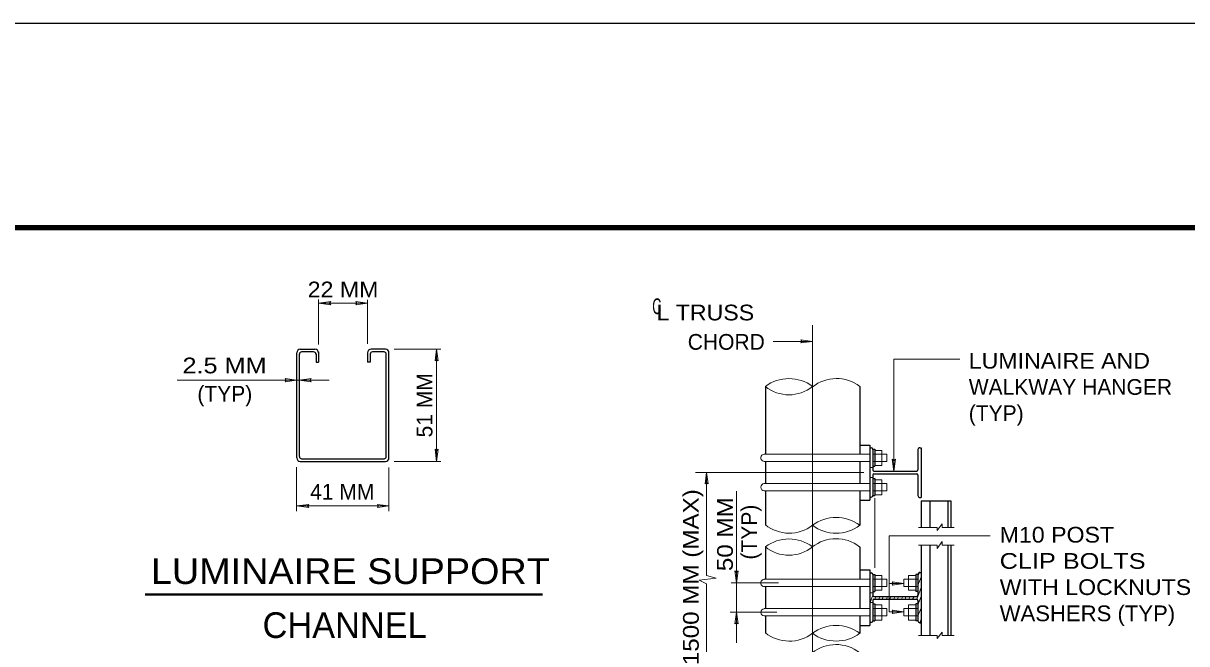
# Model space of a CAD drawing. Extents: x 312601.858 to 312602.699, y 144420.109 to 144420.704.
# Drawn here: x 312602.0414 to 312602.2633, y 144420.5851 to 144420.7035 of the extents above; entities that cross this region are included whole.
import ezdxf
from ezdxf.enums import TextEntityAlignment as Align

# ---------------------------------------------------------------- set-up
doc = ezdxf.new("R2010")
doc.units = 0
doc.header["$LTSCALE"] = 0.0012
doc.linetypes.add('DOT_DASHED', pattern=[7.7, 5, -1.2, 0.3, -1.2])
doc.linetypes.add('MEDIUM_DASHED', pattern=[4.5, 3, -1.5])
for name, color, linetype, lineweight in [('1', 7, 'Continuous', 13), ('2', 7, 'Continuous', 13), ('39', 7, 'Continuous', 13)]:
    doc.layers.add(name, color=color, linetype=linetype, lineweight=lineweight)

msp = doc.modelspace()

# ---------------------------------------------------------------- linework, layer by layer
at = {"layer": '1'}
for p, q in [((312602.0977, 144420.6508), (312602.0977, 144420.6422)), ((312602.0977, 144420.6504), (312602.0977, 144420.646)), ((312602.0977, 144420.6501), (312602.107, 144420.6501)), ((312602.107, 144420.6507), (312602.107, 144420.6423)), ((312602.121, 144420.6413), (312602.1121, 144420.6413)), ((312602.1202, 144420.6199), (312602.1202, 144420.6413)), ((312602.2074, 144420.6394), (312602.2074, 144420.618)), ((312602.22, 144420.6394), (312602.2074, 144420.6394)), ((312602.1827, 144420.6213), (312602.2009, 144420.6213)), ((312602.2051, 144420.6213), (312602.2061, 144420.6213)), ((312602.2061, 144420.6213), (312602.2061, 144420.6199)), ((312602.0935, 144420.6188), (312602.0935, 144420.6104)), ((312602.1111, 144420.6104), (312602.1111, 144420.6187)), ((312602.1121, 144420.6199), (312602.121, 144420.6199)), ((312602.2009, 144420.6199), (312602.1827, 144420.6199)), ((312602.2028, 144420.6187), (312602.2034, 144420.6187)), ((312602.2038, 144420.6191), (312602.2051, 144420.6191)), ((312602.2061, 144420.6199), (312602.2051, 144420.6199)), ((312602.2017, 144420.6178), (312602.1696, 144420.6178)), ((312602.1717, 144420.6178), (312602.1717, 144420.5981)), ((312602.2028, 144420.6168), (312602.2034, 144420.6168)), ((312602.2038, 144420.6164), (312602.2051, 144420.6164)), ((312602.2051, 144420.6135), (312602.2051, 144420.6164)), ((312602.2009, 144420.6157), (312602.1827, 144420.6157)), ((312602.1827, 144420.6143), (312602.2009, 144420.6143)), ((312602.2061, 144420.6157), (312602.2051, 144420.6157)), ((312602.2051, 144420.6143), (312602.2061, 144420.6143)), ((312602.2061, 144420.6143), (312602.2061, 144420.6157)), ((312602.2038, 144420.6135), (312602.2051, 144420.6135)), ((312602.2038, 144420.6129), (312602.2038, 144420.5996)), ((312602.0935, 144420.6114), (312602.1111, 144420.6114)), ((312602.2157, 144420.6067), (312602.2166, 144420.608)), ((312602.2166, 144420.6073), (312602.2166, 144420.608)), ((312602.2065, 144420.5912), (312602.2065, 144420.6057)), ((312602.2258, 144420.6057), (312602.2065, 144420.6057)), ((312602.2121, 144420.6073), (312602.2157, 144420.6073)), ((312602.2157, 144420.6067), (312602.2157, 144420.6073)), ((312602.2166, 144420.6073), (312602.2189, 144420.6073)), ((312602.2121, 144420.6039), (312602.2157, 144420.6039)), ((312602.2157, 144420.6033), (312602.2166, 144420.6046)), ((312602.2157, 144420.6033), (312602.2157, 144420.6039)), ((312602.2166, 144420.6039), (312602.2166, 144420.6046)), ((312602.2166, 144420.6039), (312602.2189, 144420.6039)), ((312602.2028, 144420.5992), (312602.2028, 144420.5902)), ((312602.212, 144420.598), (312602.2123, 144420.5987)), ((312602.1854, 144420.5967), (312602.1764, 144420.5967)), ((312602.1827, 144420.5974), (312602.2009, 144420.5974)), ((312602.2051, 144420.5974), (312602.2061, 144420.5974)), ((312602.2061, 144420.5974), (312602.2061, 144420.596)), ((312602.2093, 144420.5966), (312602.2065, 144420.5966)), ((312602.2093, 144420.5974), (312602.2093, 144420.596)), ((312602.2102, 144420.5974), (312602.2093, 144420.5974)), ((312602.2116, 144420.5981), (312602.2102, 144420.5981)), ((312602.2102, 144420.5981), (312602.2102, 144420.5953)), ((312602.212, 144420.5963), (312602.2126, 144420.5978)), ((312602.2009, 144420.596), (312602.1827, 144420.596)), ((312602.2028, 144420.5948), (312602.2034, 144420.5948)), ((312602.2029, 144420.593), (312602.2034, 144420.5944)), ((312602.2038, 144420.5953), (312602.2051, 144420.5953)), ((312602.2038, 144420.5936), (312602.204, 144420.5941)), ((312602.2046, 144420.5936), (312602.2047, 144420.5941)), ((312602.2061, 144420.596), (312602.2051, 144420.596)), ((312602.2052, 144420.5936), (312602.2054, 144420.5941)), ((312602.206, 144420.5936), (312602.2062, 144420.5941)), ((312602.2067, 144420.5936), (312602.2068, 144420.5941)), ((312602.2074, 144420.5936), (312602.2076, 144420.5941)), ((312602.2081, 144420.5936), (312602.2083, 144420.5941)), ((312602.2089, 144420.5936), (312602.2091, 144420.5941)), ((312602.2093, 144420.596), (312602.2102, 144420.596)), ((312602.2096, 144420.5936), (312602.2097, 144420.5941)), ((312602.2116, 144420.5953), (312602.2102, 144420.5953)), ((312602.2103, 144420.5936), (312602.2105, 144420.5941)), ((312602.211, 144420.5936), (312602.2113, 144420.5941)), ((312602.2118, 144420.5936), (312602.2126, 144420.5958)), ((312602.212, 144420.5925), (312602.2126, 144420.5941)), ((312602.2009, 144420.5918), (312602.1827, 144420.5918)), ((312602.2028, 144420.593), (312602.2034, 144420.593)), ((312602.2038, 144420.5925), (312602.2051, 144420.5925)), ((312602.2051, 144420.5896), (312602.2051, 144420.5925)), ((312602.2061, 144420.5918), (312602.2051, 144420.5918)), ((312602.2061, 144420.5904), (312602.2061, 144420.5918)), ((312602.2093, 144420.5904), (312602.2093, 144420.5918)), ((312602.2093, 144420.5918), (312602.2102, 144420.5918)), ((312602.2116, 144420.5925), (312602.2102, 144420.5925)), ((312602.212, 144420.5904), (312602.2126, 144420.5919)), ((312602.1851, 144420.5911), (312602.1762, 144420.5911)), ((312602.1827, 144420.5904), (312602.2009, 144420.5904)), ((312602.2038, 144420.5896), (312602.2051, 144420.5896)), ((312602.2051, 144420.5904), (312602.2061, 144420.5904)), ((312602.2065, 144420.5912), (312602.2093, 144420.5912)), ((312602.2102, 144420.5904), (312602.2093, 144420.5904)), ((312602.2124, 144420.5891), (312602.2126, 144420.5898)), ((312602.2121, 144420.5867), (312602.2157, 144420.5867)), ((312602.2157, 144420.5861), (312602.2166, 144420.5873)), ((312602.2157, 144420.5861), (312602.2157, 144420.5867)), ((312602.2166, 144420.5867), (312602.2166, 144420.5873)), ((312602.2166, 144420.5867), (312602.2189, 144420.5867))]:
    msp.add_line(p, q, dxfattribs=at)
at = {"layer": '1', "lineweight": 25}
for p, q in [((312602.0935, 144420.6406), (312602.0935, 144420.6206)), ((312602.0942, 144420.6413), (312602.097, 144420.6413)), ((312602.0967, 144420.6408), (312602.0945, 144420.6408)), ((312602.0977, 144420.6408), (312602.0977, 144420.6388)), ((312602.0977, 144420.6406), (312602.0977, 144420.6388)), ((312602.107, 144420.6407), (312602.107, 144420.6388)), ((312602.107, 144420.6406), (312602.107, 144420.6388)), ((312602.1104, 144420.6413), (312602.1077, 144420.6413)), ((312602.1102, 144420.6408), (312602.108, 144420.6408)), ((312602.1111, 144420.6206), (312602.1111, 144420.6406)), ((312602.094, 144420.6404), (312602.094, 144420.6208)), ((312602.0972, 144420.6404), (312602.0972, 144420.6388)), ((312602.0972, 144420.6388), (312602.0977, 144420.6388)), ((312602.1075, 144420.6388), (312602.107, 144420.6388)), ((312602.1075, 144420.6404), (312602.1075, 144420.6388)), ((312602.1106, 144420.6208), (312602.1106, 144420.6404)), ((312602.1829, 144420.6342), (312602.1829, 144420.6213)), ((312602.2009, 144420.6342), (312602.2009, 144420.6213)), ((312602.2028, 144420.623), (312602.2028, 144420.6141)), ((312602.2028, 144420.6225), (312602.2031, 144420.6225)), ((312602.2034, 144420.6222), (312602.2034, 144420.6183)), ((312602.2034, 144420.6222), (312602.2038, 144420.6222)), ((312602.2038, 144420.6222), (312602.2038, 144420.619)), ((312602.212, 144420.6222), (312602.212, 144420.6183)), ((312602.2124, 144420.6225), (312602.2126, 144420.6225)), ((312602.2126, 144420.6225), (312602.2126, 144420.613)), ((312602.0942, 144420.6199), (312602.1104, 144420.6199)), ((312602.0945, 144420.6204), (312602.1102, 144420.6204)), ((312602.1829, 144420.6199), (312602.1829, 144420.6157)), ((312602.2009, 144420.6199), (312602.2009, 144420.6157)), ((312602.2034, 144420.619), (312602.2038, 144420.619)), ((312602.2034, 144420.6173), (312602.2034, 144420.6134)), ((312602.2034, 144420.6166), (312602.2038, 144420.6166)), ((312602.2036, 144420.618), (312602.2118, 144420.618)), ((312602.2036, 144420.6175), (312602.2118, 144420.6175)), ((312602.2038, 144420.6166), (312602.2038, 144420.6134)), ((312602.212, 144420.6173), (312602.212, 144420.6134)), ((312602.1829, 144420.6143), (312602.1829, 144420.6078)), ((312602.2009, 144420.6143), (312602.2009, 144420.6077)), ((312602.2009, 144420.6125), (312602.2028, 144420.6125)), ((312602.2028, 144420.6131), (312602.2031, 144420.6131)), ((312602.2034, 144420.6134), (312602.2038, 144420.6134)), ((312602.2124, 144420.613), (312602.2126, 144420.613)), ((312602.2126, 144420.6124), (312602.2183, 144420.6124)), ((312602.2126, 144420.6124), (312602.2126, 144420.6073)), ((312602.2143, 144420.6124), (312602.2143, 144420.6073)), ((312602.2177, 144420.6124), (312602.2177, 144420.6073)), ((312602.2183, 144420.6124), (312602.2183, 144420.6073)), ((312602.1829, 144420.6036), (312602.1829, 144420.5974)), ((312602.2009, 144420.6036), (312602.2009, 144420.5974)), ((312602.2126, 144420.6039), (312602.2126, 144420.5867)), ((312602.2143, 144420.6039), (312602.2143, 144420.5867)), ((312602.2177, 144420.6039), (312602.2177, 144420.5867)), ((312602.2183, 144420.6039), (312602.2183, 144420.5867)), ((312602.2028, 144420.5986), (312602.2031, 144420.5986)), ((312602.2124, 144420.5987), (312602.2126, 144420.5987)), ((312602.2034, 144420.5983), (312602.2034, 144420.5944)), ((312602.2034, 144420.5983), (312602.2038, 144420.5983)), ((312602.2038, 144420.5983), (312602.2038, 144420.5951)), ((312602.2116, 144420.5983), (312602.2116, 144420.5951)), ((312602.212, 144420.5983), (312602.2116, 144420.5983)), ((312602.212, 144420.5983), (312602.212, 144420.5944)), ((312602.1829, 144420.596), (312602.1829, 144420.5918)), ((312602.2009, 144420.596), (312602.2009, 144420.5918)), ((312602.2034, 144420.5951), (312602.2038, 144420.5951)), ((312602.2036, 144420.5941), (312602.2118, 144420.5941)), ((312602.212, 144420.5951), (312602.2116, 144420.5951)), ((312602.2034, 144420.5934), (312602.2034, 144420.5895)), ((312602.2034, 144420.5927), (312602.2038, 144420.5927)), ((312602.2036, 144420.5936), (312602.2118, 144420.5936)), ((312602.2038, 144420.5927), (312602.2038, 144420.5895)), ((312602.212, 144420.5927), (312602.2116, 144420.5927)), ((312602.2116, 144420.5927), (312602.2116, 144420.5895)), ((312602.212, 144420.5934), (312602.212, 144420.5895)), ((312602.1829, 144420.5904), (312602.1829, 144420.5872)), ((312602.2009, 144420.5904), (312602.2009, 144420.5871)), ((312602.2009, 144420.5886), (312602.2028, 144420.5886)), ((312602.2028, 144420.5892), (312602.2031, 144420.5892)), ((312602.2034, 144420.5895), (312602.2038, 144420.5895)), ((312602.212, 144420.5895), (312602.2116, 144420.5895)), ((312602.2124, 144420.5891), (312602.2126, 144420.5891))]:
    msp.add_line(p, q, dxfattribs=at)
at = {"layer": '1', "linetype": 'MEDIUM_DASHED'}
for p, q in [((312602.2009, 144420.6213), (312602.2028, 144420.6213)), ((312602.2034, 144420.6213), (312602.2051, 144420.6213)), ((312602.2028, 144420.6199), (312602.2009, 144420.6199)), ((312602.2051, 144420.6199), (312602.2034, 144420.6199)), ((312602.2028, 144420.6157), (312602.2009, 144420.6157)), ((312602.2009, 144420.6143), (312602.2028, 144420.6143)), ((312602.2051, 144420.6157), (312602.2034, 144420.6157)), ((312602.2034, 144420.6143), (312602.2051, 144420.6143)), ((312602.2009, 144420.5974), (312602.2028, 144420.5974)), ((312602.2034, 144420.5974), (312602.2051, 144420.5974)), ((312602.212, 144420.5974), (312602.2102, 144420.5974)), ((312602.2028, 144420.596), (312602.2009, 144420.596)), ((312602.2051, 144420.596), (312602.2034, 144420.596)), ((312602.2102, 144420.596), (312602.212, 144420.596)), ((312602.2028, 144420.5918), (312602.2009, 144420.5918)), ((312602.2051, 144420.5918), (312602.2034, 144420.5918)), ((312602.2102, 144420.5918), (312602.212, 144420.5918)), ((312602.2009, 144420.5904), (312602.2028, 144420.5904)), ((312602.2034, 144420.5904), (312602.2051, 144420.5904)), ((312602.212, 144420.5904), (312602.2102, 144420.5904))]:
    msp.add_line(p, q, dxfattribs=at)
at = {"layer": '1'}
for points in [[(312602.1, 144420.6498), (312602.0977, 144420.6501), (312602.1, 144420.6504), (312602.0997, 144420.6501)], [(312602.1048, 144420.6504), (312602.107, 144420.6501), (312602.1048, 144420.6498), (312602.105, 144420.6501)], [(312602.1897, 144420.6431), (312602.1919, 144420.6428), (312602.1897, 144420.6425), (312602.1899, 144420.6428)], [(312602.1199, 144420.6391), (312602.1202, 144420.6413), (312602.1205, 144420.6391), (312602.1202, 144420.6393)], [(312602.0913, 144420.6357), (312602.0935, 144420.6354), (312602.0913, 144420.6351), (312602.0915, 144420.6354)], [(312602.0963, 144420.6351), (312602.094, 144420.6354), (312602.0963, 144420.6357), (312602.096, 144420.6354)], [(312602.1205, 144420.6222), (312602.1202, 144420.6199), (312602.1199, 144420.6222), (312602.1202, 144420.6219)], [(312602.2077, 144420.6203), (312602.2074, 144420.618), (312602.2071, 144420.6203), (312602.2074, 144420.62)], [(312602.1714, 144420.6156), (312602.1717, 144420.6178), (312602.172, 144420.6156), (312602.1717, 144420.6158)], [(312602.0958, 144420.6111), (312602.0935, 144420.6114), (312602.0958, 144420.6117), (312602.0955, 144420.6114)], [(312602.1089, 144420.6117), (312602.1111, 144420.6114), (312602.1089, 144420.6111), (312602.1091, 144420.6114)], [(312602.1777, 144420.599), (312602.1774, 144420.5967), (312602.1771, 144420.599), (312602.1774, 144420.5987)], [(312602.2071, 144420.5969), (312602.2093, 144420.5966), (312602.2071, 144420.5963), (312602.2073, 144420.5966)], [(312602.1771, 144420.5889), (312602.1774, 144420.5911), (312602.1777, 144420.5889), (312602.1774, 144420.5891)], [(312602.2071, 144420.5915), (312602.2093, 144420.5912), (312602.2071, 144420.5909), (312602.2073, 144420.5912)]]:
    msp.add_lwpolyline(points, close=True, dxfattribs=at)
for points in [[(312602.0707, 144420.6354), (312602.0935, 144420.6354), (312602.094, 144420.6354), (312602.0997, 144420.6354)], [(312602.2038, 144420.622), (312602.2051, 144420.622), (312602.2051, 144420.6191)], [(312602.1774, 144420.6142), (312602.1774, 144420.5967), (312602.1774, 144420.5911), (312602.1774, 144420.5853)], [(312602.1717, 144420.5965), (312602.1717, 144420.5772), (312602.1717, 144420.5579)], [(312602.2038, 144420.5981), (312602.2051, 144420.5981), (312602.2051, 144420.5953)], [(312602.2116, 144420.5896), (312602.2102, 144420.5896), (312602.2102, 144420.5925)]]:
    msp.add_lwpolyline(points, dxfattribs=at)
at = {"layer": '1', "lineweight": 25}
for points in [[(312602.2009, 144420.623), (312602.2028, 144420.623), (312602.2028, 144420.6125)], [(312602.2009, 144420.5992), (312602.2028, 144420.5992), (312602.2028, 144420.5886)]]:
    msp.add_lwpolyline(points, dxfattribs=at)
for centre, radius, start, end in [((312602.094195, 144420.64062), 0.00068, 90, 180), ((312602.09445, 144420.640365), 0.000425, 90, 180), ((312602.096745, 144420.640365), 0.000425, 0, 90), ((312602.097, 144420.64062), 0.00068, 0, 90), ((312602.10771, 144420.64062), 0.00068, 90, 180), ((312602.107965, 144420.640365), 0.000425, 90, 180), ((312602.110175, 144420.640365), 0.000425, 0, 90), ((312602.11043, 144420.64062), 0.00068, 0, 89.99844), ((312602.09445, 144420.620815), 0.000425, 180, 270), ((312602.110175, 144420.620815), 0.000425, 270.00156, 0), ((312602.094195, 144420.62056), 0.00068, 180, 270), ((312602.11043, 144420.62056), 0.00068, 270.00156, 359.99844), ((312602.21237, 144420.58947), 0.00037, 175.73894, 275.04245)]:
    msp.add_arc(centre, radius, start, end, dxfattribs=at)
at = {"layer": '1'}
for centre, radius, start, end in [((312602.1874, 144420.6282), 0.0075, 53.1301, 126.8699), ((312602.1874, 144420.639725), 0.007126, 230.83789, 309.16211), ((312602.196464, 144420.628399), 0.007303, 52.59302, 128.67006), ((312602.182705, 144420.62058), 0.00068, 89.99844, 269.99844), ((312602.182705, 144420.61497), 0.00068, 90.00156, 270), ((312602.187464, 144420.613509), 0.007309, 231.35969, 307.36712), ((312602.1964, 144420.601703), 0.007497, 53.11482, 126.88518), ((312602.1964, 144420.613697), 0.007497, 233.11482, 306.88518), ((312602.1874, 144420.5976), 0.0075, 53.1301, 126.8699), ((312602.1874, 144420.5976), 0.0075, 53.1301, 126.8699), ((312602.1874, 144420.5976), 0.0075, 53.1301, 126.8699), ((312602.1874, 144420.609125), 0.007126, 230.83789, 309.16211), ((312602.1874, 144420.609125), 0.007126, 230.83789, 309.16211), ((312602.1874, 144420.609125), 0.007126, 230.83789, 309.16211), ((312602.182705, 144420.596695), 0.00068, 89.99844, 269.99844), ((312602.182705, 144420.591085), 0.00068, 90.00156, 270), ((312602.1964, 144420.581103), 0.007497, 53.11482, 126.88518), ((312602.187464, 144420.592909), 0.007309, 231.35969, 307.36712), ((312602.1964, 144420.593097), 0.007497, 233.11482, 306.88518)]:
    msp.add_arc(centre, radius, start, end, dxfattribs=at)
at = {"layer": '1', "lineweight": 25}
for centre, major_axis, ratio, start_param, end_param in [((312602.203105, 144420.622195), (0, 0.000305), 0.967213, 4.712389, 6.2831853), ((312602.21237, 144420.622195), (-0.00037, 0), 0.824324, 4.6314849, 6.2831853), ((312602.203615, 144420.618285), (0, -0.000285), 0.754386, 4.712389, 6.2831853), ((312602.203615, 144420.617265), (0, -0.000235), 0.914894, 3.1415927, 4.712389), ((312602.211775, 144420.618285), (0, -0.000285), 0.789474, 6.2831853, 7.8539816), ((312602.211775, 144420.617265), (0, 0.000235), 0.957447, 4.712389, 6.2831853), ((312602.203105, 144420.613355), (0.000295, 0), 0.864407, 4.712389, 6.4578575), ((312602.21237, 144420.613355), (-0.00037, 0), 0.959459, 6.1570972, 7.9348857), ((312602.203105, 144420.59831), (0.000295, 0), 0.983051, 6.2831853, 7.8539816), ((312602.21237, 144420.59831), (0, -0.00039), 0.948718, 3.0606885, 4.712389), ((312602.203615, 144420.5944), (0, -0.0003), 0.716667, 4.712389, 6.2831853), ((312602.211775, 144420.5944), (0, -0.0003), 0.75, 6.2831853, 7.8539816), ((312602.203615, 144420.59338), (0, -0.00022), 0.977273, 3.1415927, 4.712389), ((312602.211775, 144420.59338), (-0.000225, 0), 0.977778, 3.1415927, 4.712389), ((312602.203105, 144420.58947), (0.000295, 0), 0.864407, 4.712389, 6.400294)]:
    msp.add_ellipse(centre, major_axis=major_axis, ratio=ratio, start_param=start_param, end_param=end_param, dxfattribs=at)
at = {"layer": '1'}
for centre in [(312602.196464, 144420.597799), (312602.196464, 144420.597799), (312602.196464, 144420.577599)]:
    msp.add_ellipse(centre, major_axis=(-0.004613, 0.005762), ratio=0.989423, start_param=4.9552139, end_param=6.2831853, dxfattribs=at)
at = {"layer": '2', "linetype": 'DOT_DASHED'}
msp.add_line((312602.1919, 144420.6459), (312602.1919, 144420.4762), dxfattribs=at)
at = {"layer": '2'}
msp.add_line((312602.1844, 144420.6428), (312602.1919, 144420.6428), dxfattribs=at)
at = {"layer": '2', "lineweight": 40}
msp.add_line((312602.0646, 144420.5945), (312602.1404, 144420.5945), dxfattribs=at)
at = {"layer": '2'}
msp.add_lwpolyline([(312602.1717, 144420.5965), (312602.1703, 144420.5972), (312602.1735, 144420.5976), (312602.1717, 144420.5981)], dxfattribs=at)
at = {"layer": '39', "lineweight": 25}
msp.add_line((312601.8578, 144420.7035), (312602.6988, 144420.7035), dxfattribs=at)
at = {"layer": '39', "lineweight": 158}
msp.add_line((312601.9088, 144420.6645), (312602.6838, 144420.6645), dxfattribs=at)

# ---------------------------------------------------------------- texts
at = {"layer": '1'}
for s, width, p in [('C', 0.6, (312602.1622, 144420.648)), ('L TRUSS', 1.1, (312602.17145, 144420.6468))]:
    msp.add_text(s, height=0.003, dxfattribs=dict(at, width=width)).set_placement(p, align=Align.CENTER)
at = {"layer": '2'}
for s, width, p in [('22 MM', 1.1, (312602.10235, 144420.6512)), ('2.5 MM', 1.2, (312602.07975, 144420.6367))]:
    msp.add_text(s, height=0.003, dxfattribs=dict(at, width=width)).set_placement(p, align=Align.CENTER)
for s, p in [('CHORD', (312602.17545, 144420.6412)), ('(TYP)', (312602.0798, 144420.6313)), ('41 MM', (312602.1022, 144420.6126))]:
    msp.add_text(s, height=0.003, dxfattribs=at).set_placement(p, align=Align.CENTER)
for s, height, width, p in [('LUMINAIRE AND', 0.003, 1.1, (312602.2217, 144420.6376)), ('M10 POST', 0.003, 1.1, (312602.2276, 144420.6044)), ('LUMINAIRE SUPPORT', 0.0049, 1.1, (312602.0657, 144420.5965)), ('CLIP BOLTS ', 0.003, 1.2, (312602.2276, 144420.5994)), ('WITH LOCKNUTS AND', 0.003, 1.1, (312602.2276, 144420.5944)), ('WASHERS (TYP)', 0.003, 1.05, (312602.2276, 144420.5894))]:
    msp.add_text(s, height=height, dxfattribs=dict(at, width=width)).set_placement(p)
for s, p in [('51 MM', (312602.1194, 144420.6306)), ('(TYP)', (312602.1813, 144420.6064))]:
    msp.add_text(s, height=0.003, rotation=90, dxfattribs=at).set_placement(p, align=Align.CENTER)
for s, height, p in [('WALKWAY HANGER', 0.003, (312602.2217, 144420.6326)), ('(TYP)', 0.003, (312602.2217, 144420.6276)), ('CHANNEL', 0.0049, (312602.087, 144420.5862))]:
    msp.add_text(s, height=height, dxfattribs=at).set_placement(p)
at = {"layer": '2', "width": 1.15}
for s, p in [('1500 MM (MAX)', (312602.1702, 144420.5978)), ('50 MM', (312602.1767, 144420.606))]:
    msp.add_text(s, height=0.003, rotation=90, dxfattribs=at).set_placement(p, align=Align.CENTER)

doc.saveas('drawing.dxf')
